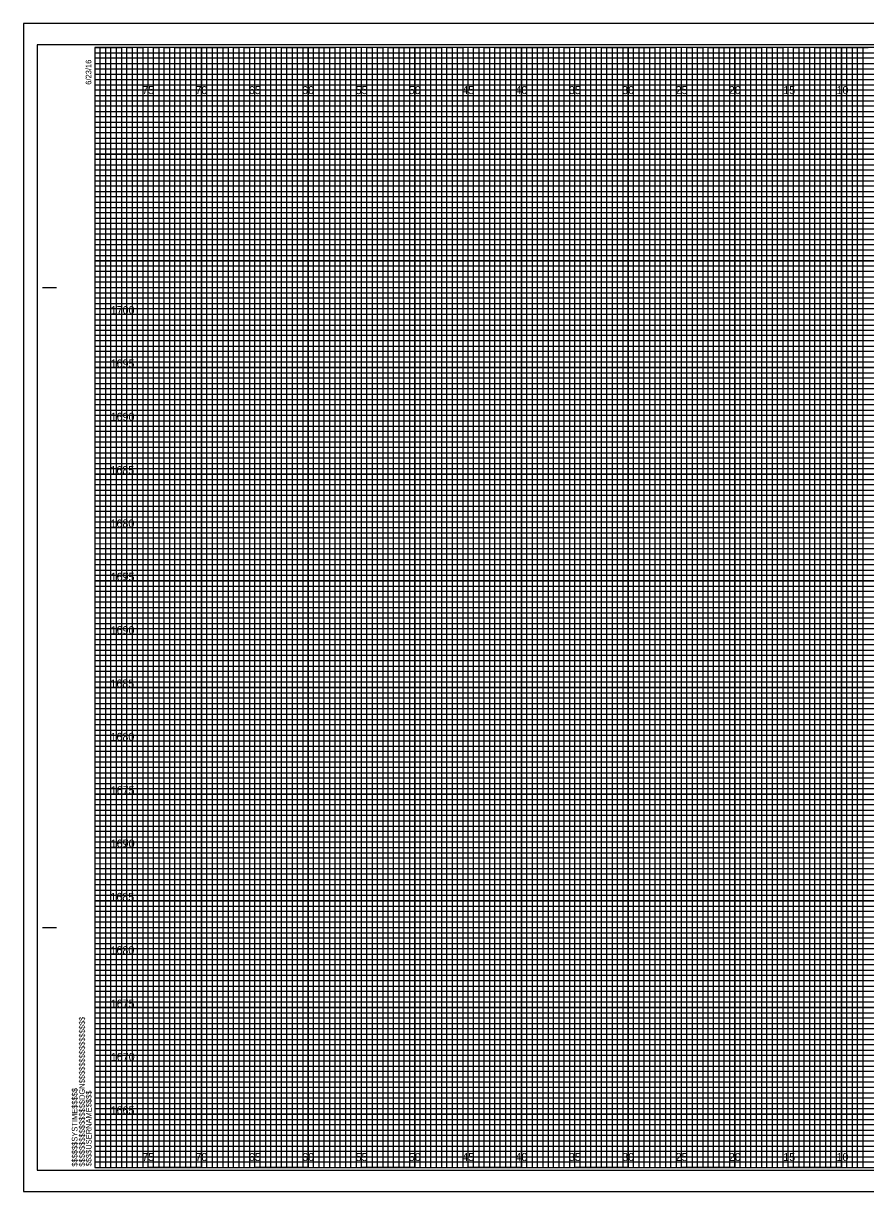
# Model space of a CAD drawing. Extents: x -7 to 162, y -2 to 217.
# Drawn here: x -6.7 to 72.2, y -2.3 to 107.3 of the extents above; entities that cross this region are included whole.
import ezdxf

# ---------------------------------------------------------------- set-up
doc = ezdxf.new("R2010")
doc.units = 0
for name, color, linetype in [('Raster_Level_0', 7, 'Continuous'), ('Scratch_Level_3', 7, 'Continuous'), ('Sheet Cross Section CELL', 7, 'Continuous'), ('Sheet Cross Section Grid Major CELL', 7, 'Continuous'), ('Sheet Cross Section Grid Middle CELL', 7, 'Continuous'), ('Sheet Cross Section Grid Minor 1 CELL', 7, 'Continuous'), ('Sheet Cross Section Grid Minor 2 CELL', 7, 'Continuous'), ('Sheet Cutting Line CELL', 7, 'Continuous'), ('Sheet DOT Grid CELL', 7, 'Continuous'), ('Sheet Plot Border Inside CELL', 7, 'Continuous'), ('Sheet Plot Border Outside CELL', 7, 'Continuous')]:
    doc.layers.add(name, color=color, linetype=linetype)

msp = doc.modelspace()

# ---------------------------------------------------------------- linework, layer by layer
at = {"layer": 'Sheet Cross Section CELL'}
for p, q in [((-4.9, 82.5), (-3.65, 82.5)), ((-4.85, 82.5), (-3.6, 82.5)), ((-4.9, 22.5), (-3.65, 22.5)), ((-4.85, 22.5), (-3.6, 22.5)), ((0, 0), (0, 0)), ((0, 0), (0, 0)), ((0, 0), (0, 0)), ((0, 0), (0, 0)), ((0, 0), (0, 0)), ((0, 0), (0, 0)), ((0, 0), (0, 0))]:
    msp.add_line(p, q, dxfattribs=at)
msp.add_lwpolyline([(160, 105), (0, 105), (0, 0), (160, 0)], close=True, dxfattribs=at)
at = {"layer": 'Sheet Cross Section Grid Major CELL'}
for p, q in [((5, 105), (0, 105)), ((5, 0), (5, 105)), ((15, 105), (10, 105)), ((10, 105), (10, 0)), ((15, 0), (15, 105)), ((25, 105), (20, 105)), ((20, 105), (20, 0)), ((25, 0), (25, 105)), ((35, 105), (30, 105)), ((30, 105), (30, 0)), ((35, 0), (35, 105)), ((45, 105), (40, 105)), ((40, 105), (40, 0)), ((45, 0), (45, 105)), ((55, 105), (50, 105)), ((50, 105), (50, 0)), ((55, 0), (55, 105)), ((65, 105), (60, 105)), ((60, 105), (60, 0)), ((65, 0), (65, 105)), ((75, 105), (70, 105)), ((70, 105), (70, 0)), ((10, 0), (5, 0)), ((20, 0), (15, 0)), ((30, 0), (25, 0)), ((40, 0), (35, 0)), ((50, 0), (45, 0)), ((60, 0), (55, 0)), ((70, 0), (65, 0))]:
    msp.add_line(p, q, dxfattribs=at)
for points in [[(0, 100), (160, 100), (160, 95), (0, 95)], [(0, 90), (160, 90), (160, 85), (0, 85)], [(0, 80), (160, 80), (160, 75), (0, 75)], [(0, 70), (160, 70), (160, 65), (0, 65)], [(0, 60), (160, 60), (160, 55), (0, 55)], [(0, 50), (160, 50), (160, 45), (0, 45)], [(0, 40), (160, 40), (160, 35), (0, 35)], [(0, 30), (160, 30), (160, 25), (0, 25)], [(0, 20), (160, 20), (160, 15), (0, 15)], [(0, 10), (160, 10), (160, 5), (0, 5)]]:
    msp.add_lwpolyline(points, dxfattribs=at)
at = {"layer": 'Sheet Cross Section Grid Middle CELL'}
for points in [[(0, 105), (2.5, 105), (2.5, 0), (7.5, 0), (7.5, 105), (12.5, 105), (12.5, 0), (17.5, 0), (17.5, 105), (22.5, 105), (22.5, 0), (27.5, 0), (27.5, 105), (32.5, 105), (32.5, 0), (37.5, 0), (37.5, 105), (42.5, 105), (42.5, 0), (47.5, 0), (47.5, 105), (52.5, 105), (52.5, 0), (57.5, 0), (57.5, 105), (62.5, 105), (62.5, 0), (67.5, 0), (67.5, 105), (72.5, 105)], [(0, 102.5), (137.5, 102.5)], [(0, 92.5), (160, 92.5), (160, 97.5), (0, 97.5)], [(0, 82.5), (160, 82.5), (160, 87.5), (0, 87.5)], [(0, 72.5), (160, 72.5), (160, 77.5), (0, 77.5)], [(0, 62.5), (160, 62.5), (160, 67.5), (0, 67.5)], [(0, 52.5), (160, 52.5), (160, 57.5), (0, 57.5)], [(0, 42.5), (160, 42.5), (160, 47.5), (0, 47.5)], [(0, 32.5), (160, 32.5), (160, 37.5), (0, 37.5)], [(0, 22.5), (160, 22.5), (160, 27.5), (0, 27.5)], [(0, 12.5), (160, 12.5), (160, 17.5), (0, 17.5)], [(0, 2.5), (160, 2.5), (160, 7.5), (0, 7.5)]]:
    msp.add_lwpolyline(points, dxfattribs=at)
at = {"layer": 'Sheet Cross Section Grid Minor 1 CELL'}
for p, q in [((0, 104.5), (130, 104.5)), ((130, 103.99), (0, 103.99)), ((0, 103.99), (0, 103.5)), ((0, 103.5), (130, 103.5)), ((130, 102.95), (0, 102.95)), ((0, 102.95), (0, 102)), ((0, 102), (160, 102))]:
    msp.add_line(p, q, dxfattribs=at)
for points in [[(0, 101.5), (135, 101.5), (160, 101.5), (160, 101), (0, 101)], [(0, 100.5), (160, 100.5), (160, 99.5), (0, 99.5)], [(0, 99), (160, 99), (160, 98.5), (0, 98.49)], [(0, 98), (160, 98), (160, 97), (0, 97)], [(0, 96.5), (160, 96.5), (160, 96), (0, 96)], [(0, 95.5), (160, 95.5), (160, 94.5), (0, 94.5)], [(0, 94), (160, 94), (160, 93.5), (0, 93.5)], [(0, 93), (160, 93), (160, 92), (0, 92)], [(0, 91.5), (160, 91.5), (160, 91), (0, 91)], [(0, 90.5), (160, 90.5), (160, 89.5), (0, 89.5)], [(0, 89), (160, 89), (160, 88.5), (0, 88.5)], [(0, 88), (160, 88), (160, 86.98), (160, 86.5), (160, 86), (0, 86)], [(0, 87), (160, 87), (160, 86.5), (0, 86.5)], [(0, 85.5), (160, 85.5), (160, 84.5), (0, 84.52)], [(0, 84.52), (160, 84.5), (160, 84), (0, 84)], [(0, 83.5), (160, 83.5), (160, 83), (0, 83)], [(0, 82), (160, 82), (160, 81.5), (0, 81.5)], [(0, 81), (160, 81), (160, 80.5), (0, 80.5)], [(-0.04, 79.45), (160, 79.45), (160, 78.94), (-0.04, 78.94)], [(0, 78.5), (160, 78.5), (160, 78), (0, 78)], [(0, 77), (160, 77), (160, 76.5), (0, 76.5)], [(0, 76), (160, 76), (160, 75.5), (0, 75.5)], [(0, 74.5), (160, 74.5), (160, 74), (0, 74)], [(0, 73.5), (160, 73.5), (160, 73), (0, 73)], [(0, 72), (160, 72), (160, 71.5), (0, 71.5)], [(0, 71), (160, 71), (160, 70.5), (0, 70.5)], [(0, 69.5), (160, 69.5), (160, 68.99), (0, 69)], [(0, 68.5), (160, 68.5), (160, 68), (0, 68)], [(0, 67), (160, 67), (160, 66.5), (0, 66.5)], [(0, 66), (160, 66), (160, 65.5), (0, 65.5)], [(0, 64.5), (160, 64.5), (160, 64), (0, 64)], [(0, 63.5), (160, 63.5), (160, 63), (0, 63)], [(0, 62), (160, 62), (160, 61.5), (0, 61.5)], [(0, 61), (160, 61), (160, 60.5), (0, 60.5)], [(0, 59.5), (160, 59.5), (160, 59), (0, 59)], [(0, 58.5), (160.03, 58.45), (160, 58), (0, 58)], [(0, 57), (160, 57), (160, 56.5), (0, 56.5)], [(0, 56), (160, 56), (160, 55.5), (0, 55.5)], [(0, 54.5), (160, 54.5), (160, 54), (0, 54)], [(0, 53.5), (160, 53.5), (160, 53), (0, 53)], [(0, 52), (160, 52), (160, 51.5), (0, 51.5)], [(0, 51), (160, 51), (160, 50.5), (0, 50.5)], [(0, 49.5), (160, 49.5), (160, 49), (0, 49)], [(0, 48.5), (160, 48.5), (160, 48), (0, 48)], [(0, 47), (160, 47), (160, 46.5), (0, 46.5)], [(0, 46), (160, 46), (160, 45.5), (0, 45.5)], [(0, 44.5), (160, 44.5), (160, 44), (0, 44)], [(0, 43.5), (160, 43.5), (160, 43), (0, 43)], [(0, 42), (160, 42), (160, 41.5), (0, 41.5)], [(0, 41), (160, 41), (160, 40.5), (0, 40.5)], [(0, 39.5), (160, 39.5), (160, 38.99), (0, 39)], [(0, 38.5), (160, 38.5), (160, 38), (0, 38)], [(0, 37), (160, 37), (160, 36.5), (0, 36.5)], [(0, 36), (160, 36), (160, 35.5), (0, 35.5)], [(0, 34.5), (160, 34.5), (160, 34), (0, 34)], [(0, 33.5), (160, 33.5), (160, 33), (0, 33)], [(0, 32), (160, 32), (160, 31.5), (0, 31.5)], [(0, 31), (160, 31), (160, 30.5), (0, 30.5)], [(0, 29.5), (160, 29.5), (160, 29), (0, 29)], [(0, 28.5), (160.03, 28.46), (160, 28), (0, 28)], [(0, 27), (160, 27), (160, 26.5), (0, 26.5)], [(0, 26), (160, 26), (160, 25.5), (0, 25.5)], [(0, 24.5), (160, 24.5), (160, 24), (0, 24)], [(0, 23.5), (160, 23.5), (160, 23), (0, 23)], [(0, 22), (160, 22), (160, 21.5), (0, 21.5)], [(0, 21), (160, 21), (160, 20.5), (0, 20.5)], [(0, 19.5), (160, 19.5), (160, 19), (0, 19)], [(0, 18.5), (160, 18.5), (160, 18), (0, 18)], [(0, 17), (160, 17), (160, 16.5), (0, 16.5)], [(0, 16), (160, 16), (160, 15.5), (0, 15.5)], [(0, 14.5), (160, 14.5), (160, 14), (0, 14)], [(0, 13.5), (160, 13.5), (160, 13), (0, 13)], [(0, 12), (160, 12), (160, 11.5), (0, 11.5)], [(0, 11), (160, 11), (160, 10.5), (0, 10.5)], [(0, 9.5), (160, 9.5), (160, 9), (0, 9)], [(0, 8.5), (160, 8.5), (160, 8), (0, 8)], [(0, 7), (160, 7), (160, 6.5), (0, 6.5)], [(0, 6), (160, 6), (160, 5.5), (0, 5.5)], [(0, 4.5), (160, 4.5), (160, 4), (0, 4)], [(0, 3.5), (160, 3.5), (160, 3), (0, 3)], [(0, 2), (160, 2), (160, 1.5), (0, 1.5)], [(0, 1), (160, 1), (160, 0.5), (0, 0.5)]]:
    msp.add_lwpolyline(points, dxfattribs=at)
at = {"layer": 'Sheet Cross Section Grid Minor 2 CELL'}
for points in [[(0, 0), (0.5, 0), (0.5, 105), (1, 105), (1, 0)], [(1, 0), (1.5, 0), (1.5, 105), (2, 105), (2, 0)], [(2.5, 0), (3, 0), (3, 105), (3.5, 105), (3.5, 0)], [(3.5, 0), (4, 0), (4, 105), (4.5, 105), (4.5, 0)], [(5, 0), (5.5, 0), (5.5, 105), (6, 105), (6, 0)], [(6, 0), (6.5, 0), (6.5, 105), (7, 105), (7, 0)], [(7.5, 0), (8, 0), (8, 105), (8.5, 105), (8.5, 0)], [(8.5, 0), (9, 0), (9, 105), (9.5, 105), (9.5, 0)], [(10, 0), (10.5, 0), (10.5, 105), (11, 105), (11, 0)], [(11, 0), (11.5, 0), (11.5, 105), (12, 105), (12, 0)], [(12.5, 0), (13, 0), (13, 105), (13.5, 105), (13.5, 0)], [(13.5, 0), (14, 0), (14, 105), (14.5, 105), (14.5, 0)], [(15, 0), (15.5, 0), (15.5, 105), (16, 105), (16, 0)], [(16, 0), (16.5, 0), (16.5, 105), (17, 105), (17, 0)], [(17.5, 0), (18, 0), (18, 105), (18.5, 105), (18.5, 0)], [(18.5, 0), (19, 0), (19, 105), (19.5, 105), (19.5, 0)], [(20, 0), (20.5, 0), (20.5, 105), (21, 105), (21, 0)], [(21, 0), (21.5, 0), (21.5, 105), (22, 105), (22, 0)], [(22.5, 0), (23, 0), (23, 105), (23.5, 105), (23.5, 0)], [(23.5, 0), (24, 0), (24, 105), (24.5, 105), (24.5, 0)], [(25, 0), (25.5, 0), (25.5, 105), (26, 105), (26, 0)], [(26, 0), (26.5, 0), (26.5, 105), (27, 105), (27, 0)], [(27.5, 0), (28, 0), (28, 105), (28.5, 105), (28.5, 0)], [(28.5, 0), (29, 0), (29, 105), (29.5, 105), (29.5, 0)], [(30, 0), (30.5, 0), (30.5, 105), (31, 105), (31, 0)], [(31, 0), (31.5, 0), (31.5, 105), (32, 105), (32, 0)], [(32.5, 0), (33, 0), (33, 105), (33.5, 105), (33.5, 0)], [(33.5, 0), (34, 0), (34, 105), (34.5, 105), (34.5, 0)], [(35, 0), (35.5, 0), (35.5, 105), (36, 105), (36, 0)], [(36, 0), (36.5, 0), (36.5, 105), (37, 105), (37, 0)], [(37.5, 0), (38, 0), (38, 105), (38.5, 105), (38.5, 0)], [(38.5, 0), (39, 0), (39, 105), (39.5, 105), (39.5, 0)], [(40, 0), (40.5, 0), (40.5, 105), (41, 105), (41, 0)], [(41, 0), (41.5, 0), (41.5, 105), (42, 105), (42, 0)], [(42.5, 0), (43, 0), (43, 105), (43.5, 105), (43.5, 0)], [(43.5, 0), (44, 0), (44, 105), (44.5, 105), (44.5, 0)], [(45, 0), (45.5, 0), (45.5, 105), (46, 105), (46, 0)], [(46, 0), (46.5, 0), (46.5, 105), (47, 105), (47, 0)], [(47.5, 0), (48, 0), (48, 105), (48.5, 105), (48.5, 0)], [(48.5, 0), (49, 0), (49, 105), (49.5, 105), (49.5, 0)], [(50, 0), (50.5, 0), (50.5, 105), (51, 105), (51, 0)], [(51, 0), (51.5, 0), (51.5, 105), (52, 105), (52, 0)], [(52.5, 0), (53, 0), (53, 105), (53.5, 105), (53.5, 0)], [(53.5, 0), (54, 0), (54, 105), (54.5, 105), (54.5, 0)], [(55, 0), (55.5, 0), (55.5, 105), (56, 105), (56, 0)], [(56, 0), (56.5, 0), (56.5, 105), (57, 105), (57, 0)], [(57.5, 0), (58, 0), (58, 105), (58.5, 105), (58.5, 0)], [(58.5, 0), (59, 0), (59, 105), (59.5, 105), (59.5, 0)], [(60, 0), (60.5, 0), (60.5, 105), (61, 105), (61, 0)], [(61, 0), (61.5, 0), (61.5, 105), (62, 105), (62, 0)], [(62.5, 0), (63, 0), (63, 105), (63.5, 105), (63.5, 0)], [(63.5, 0), (64, 0), (64, 105), (64.5, 105), (64.5, 0)], [(65, 0), (65.5, 0), (65.5, 105), (66, 105), (66, 0)], [(66, 0), (66.5, 0), (66.5, 105), (67, 105), (67, 0)], [(67.5, 0), (68, 0), (68, 105), (68.5, 105), (68.5, 0)], [(68.5, 0), (69, 0), (69, 105), (69.5, 105), (69.5, 0)], [(70, 0), (70.5, 0), (70.5, 105), (71, 105), (71, 0)], [(71, 0), (71.5, 0), (71.5, 105), (72, 105), (72, 0)]]:
    msp.add_lwpolyline(points, dxfattribs=at)
at = {"layer": 'Sheet Cutting Line CELL'}
for p, q in [((161.65, 107.25), (-6.7, 107.25)), ((-6.7, 107.25), (-6.7, -2.25)), ((-6.7, -2.25), (161.65, -2.25))]:
    msp.add_line(p, q, dxfattribs=at)
at = {"layer": 'Sheet DOT Grid CELL'}
for p, q in [((5, 0), (5, 105)), ((10, 0), (10, 105)), ((15, 0), (15, 105)), ((20, 0), (20, 105)), ((25, 0), (25, 105)), ((30, 0), (30, 105)), ((35, 0), (35, 105)), ((40, 0), (40, 105)), ((45, 0), (45, 105)), ((50, 0), (50, 105)), ((55, 0), (55, 105)), ((60, 0), (60, 105)), ((65, 0), (65, 105)), ((70, 0), (70, 105)), ((0, 100), (160, 100)), ((0, 95), (160, 95)), ((0, 90), (160, 90)), ((0, 85), (160, 85)), ((0, 80), (160, 80)), ((0, 75), (160, 75)), ((0, 70), (160, 70)), ((0, 65), (160, 65)), ((0, 60), (160, 60)), ((0, 55), (160, 55)), ((0, 50), (160, 50)), ((0, 45), (160, 45)), ((0, 40), (160, 40)), ((0, 35), (160, 35)), ((0, 30), (160, 30)), ((0, 25), (160, 25)), ((0, 20), (160, 20)), ((0, 15), (160, 15)), ((0, 10), (160, 10)), ((0, 5), (160, 5))]:
    msp.add_line(p, q, dxfattribs=at)
at = {"layer": 'Sheet Plot Border Inside CELL'}
msp.add_lwpolyline([(-5.4, -0.25), (161.2, -0.25), (161.2, 105.25), (-5.4, 105.25)], close=True, dxfattribs=at)
at = {"layer": 'Sheet Plot Border Outside CELL'}
msp.add_lwpolyline([(-6.7, -2.25), (161.65, -2.25), (161.65, 107.25), (-6.7, 107.25)], close=True, dxfattribs=at)

# ---------------------------------------------------------------- texts
at = {"layer": 'Raster_Level_0'}
for s, p in [('75', (4.44, 100.62)), ('70', (9.43, 100.62)), ('65', (14.44, 100.62)), ('60', (19.43, 100.62)), ('55', (24.44, 100.62)), ('50', (29.43, 100.62)), ('45', (34.44, 100.62)), ('40', (39.43, 100.62)), ('35', (44.44, 100.62)), ('30', (49.43, 100.62)), ('25', (54.44, 100.62)), ('20', (59.43, 100.62)), ('15', (64.53, 100.62)), ('10', (69.52, 100.62)), ('75', (4.44, 0.62)), ('70', (9.43, 0.62)), ('65', (14.44, 0.62)), ('60', (19.43, 0.62)), ('55', (24.44, 0.62)), ('50', (29.43, 0.62)), ('45', (34.44, 0.62)), ('40', (39.43, 0.62)), ('35', (44.44, 0.62)), ('30', (49.43, 0.62)), ('25', (54.44, 0.62)), ('20', (59.43, 0.62)), ('15', (64.53, 0.62)), ('10', (69.52, 0.62))]:
    msp.add_text(s, height=0.75, dxfattribs=at).set_placement(p)
at = {"layer": 'Scratch_Level_3'}
for s, p in [('1700', (1.49, 80)), ('1695', (1.48, 75)), ('1690', (1.48, 70)), ('1685', (1.46, 65)), ('1680', (1.47, 60)), ('1695', (1.48, 55)), ('1675', (1.49, 55)), ('1690', (1.48, 50)), ('1685', (1.46, 45)), ('1680', (1.47, 40)), ('1675', (1.49, 35)), ('1690', (1.48, 30)), ('1670', (1.5, 30)), ('1685', (1.46, 25)), ('1680', (1.47, 20)), ('1675', (1.49, 15)), ('1670', (1.5, 10)), ('1665', (1.48, 5))]:
    msp.add_text(s, height=0.75, dxfattribs=at).set_placement(p)
at = {"layer": 'Sheet Cross Section CELL'}
for s, p in [('6/23/16', (-0.33, 101.5)), ('$$$$$$$$$$$$$$$$DGN$$$$$$$$$$$$$$$$', (-0.94, 0.09)), ('$$$$$$SYSTIME$$$$$', (-1.63, 0.09)), ('$$$$USERNAME$$$$', (-0.31, 0.12))]:
    msp.add_text(s, height=0.525, rotation=90, dxfattribs=at).set_placement(p)

doc.saveas('drawing.dxf')
